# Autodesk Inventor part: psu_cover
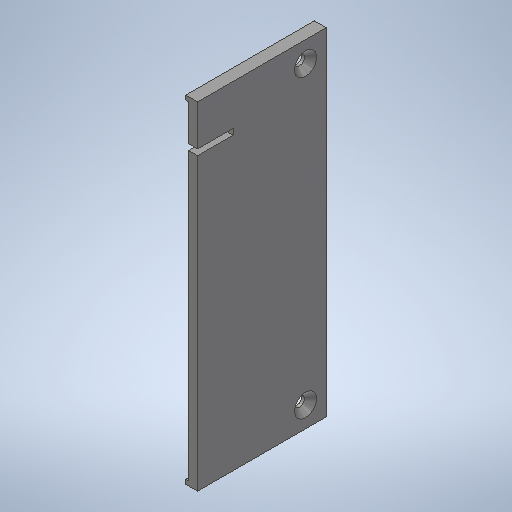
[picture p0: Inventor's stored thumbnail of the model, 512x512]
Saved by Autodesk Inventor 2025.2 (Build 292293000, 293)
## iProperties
Created: 2025-04
Part Number: psu_cover
Material: 1.0037 S235JR
Document SubType Name: Modeling
Designer: BennF
Density: 7.85 g/cm^3
Appearance: Stahl
Author: BennF
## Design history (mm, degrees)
sketch "Sketch2"
  geometry: L1 (-21.75, 57)-(21.75, 57); L2 (21.75, 57)-(21.75, -57); L3 (21.75, -57)-(-21.75, -57); L4 (-21.75, -57)-(-21.75, 57); 3 further points
  constraints: 8 end point, 2 midpoint, 2 parallel, 1 horizontal, 1 horizontal alignment, 1 perpendicular, 1 vertical alignment
  dimensions: "d0" = 114 distance of L1.end L2.end; "d1" = 43.5 distance of L1.start L1.end
extrude "Extrusion1" new body sketch "Sketch2" distance "d2" = 3; taper "d3" = 0 deg
sketch "Sketch3"
  geometry: L1 (57, 21.75)-(57, -21.75) reference; L2 (-57, 21.75)-(57, 21.75) reference; L3 (-57, -21.75)-(-57, 21.75) reference; L4 (55.5, -21.75)-(55.5, 20.25); L5 (55.5, 20.25)-(-55.5, 20.25); L6 (-55.5, 20.25)-(-55.5, -21.75); L7 (57, -21.75)-(-57, -21.75) reference; 1 further point
  constraints: 6 end point, 2 other
  dimensions: "d4" = 1.5 distance between parallel lines of L1 L4
extrude "Extrusion2" join sketch "Sketch3" distance "d5" = 1; taper "d6" = 0 deg
sketch "Sketch4"
  geometry: L1 (-50, 14.75)-(50, 14.75); L2 (57, 21.75)-(-57, 21.75) reference; L3 (-57, 21.75)-(-57, -21.75) reference; 2 further points
  constraints: 2 end point, 1 horizontal, 1 horizontal alignment, 1 midpoint, 1 vertical alignment
  dimensions: "d14" = 7 distance between parallel lines of L2 L1; "d15" = 7 distance from line of L3 L1.start (= d14)
hole "Hole1" sketch "Sketch4" at (-50, 14.75), (50, 14.75) diameter "d7" = 3.4; stored, may be unused: countersink angle "d11" = 90 deg, drill point angle "d13" = 118 deg; dims "d8" = 6, "d9" = 7.5, "d10" = 2, "d12" = 8
sketch "Sketch5"
  geometry: L1 (-57, -21.75)-(57, -21.75) reference; L2 (-41.25, -21.75)-(-41.25, -9.75); L3 (-41.25, -9.75)-(-43.25, -9.75); L4 (-43.25, -9.75)-(-43.25, -21.75); L5 (-57, 21.75)-(-57, -21.75) reference; 2 further points
  constraints: 6 end point, 3 perpendicular, 2 point on line, 1 midpoint
  dimensions: "d16" = 14.75 distance from line of point (-42.25, -9.75) L5; "d17" = 12 distance of L2.start L2.end; "d18" = 2 distance of L2.end L3.end
extrude "Extrusion3" cut sketch "Sketch5" stored distance "d19" = 1; taper "d20" = 0 deg
body "Solid1"
